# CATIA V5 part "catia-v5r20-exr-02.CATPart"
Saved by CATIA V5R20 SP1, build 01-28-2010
Part number: Part1
Bounding box of the stored display mesh (mm): x 0 to 0, y -1000000 to 1000000, z 0 to 249.999
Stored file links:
  D:\v5_r20\psrt_files_downloaded\c03-catia-v5r20-prt\catia-v5r20-exr-02.CATPart
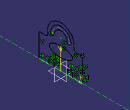
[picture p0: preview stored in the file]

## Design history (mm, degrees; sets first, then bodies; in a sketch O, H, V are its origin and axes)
Body1 (main body)
  Sketch1 on yz-plane, origin (0, 0, 0), H (0, 1, 0), V (0, 0, 1)
    line L1 (0, 0) -> (40, 0)
    point P1 (40, 0)
    line L2 (40, 0) -> (40, 30)
    point P2 (40, 30)
    line L3 (40, 30) -> (70, 30)
    point P3 (70, 30)
    line L4 (70, 30) -> (70, 0)
    point P4 (70, 0)
    line L5 (70, 0) -> (130, 0)
    point P5 (130, 0)
    line L6 (130, 0) -> (130, 140)
    line L7 (130, 140) -> (80.0487, 140)
    line L8 (80.0487, 140) -> (80.0487, 170)
    arc A1 centre (0.0487, 170) radius 80 from (80.0487, 170) to (-79.9513, 170) ccw
    line L9 (-79.9513, 170) -> (-79.9513, 140)
    point P11 (-79.9513, 140)
    line L10 (-79.9513, 140) -> (-130, 140)
    line L11 (-130, 140) -> (-130, 0)
    point P13 (-130, 0)
    point P14 (0, 0)
    construction line L12 through (0, 0) direction (-1, 0)
    point P17 (-40, 0)
    line L13 (0, 0) -> (-40, 0)
    point P18 (-40, 30)
    point P19 (-70, 30)
    point P20 (-70, 0)
    point P21 (-130, 0)
    line L14 (-40, 0) -> (-40, 30)
    line L15 (-40, 30) -> (-70, 30)
    line L16 (-70, 30) -> (-70, 0)
    line L17 (-70, 0) -> (-130, 0)
    construction arc A2 centre (0.0487, 170) radius 49.9513 from (50, 170) to (-49.9026, 170) ccw
    arc A3 centre (50, 170) radius 10.8276 from (60.8276, 170) to (39.1724, 170) cw
    arc A4 centre (-49.9026, 170) radius 10.7303 from (-39.1724, 170) to (-60.6329, 170) cw
    arc A5 centre (0, 170) radius 39.1724 from (39.1724, 170) to (-39.1724, 170) ccw
    arc A6 centre (0.0974, 170) radius 60.7303 from (-60.6329, 170) to (60.8276, 170) cw
    point P28 (0, 100)
    ellipse A7 centre (0, 100) semi-axes 70, 30 rotation 0
    point P29 (70, 100)
    point P30 (0, 130)
    horizontal: L1 H, L3 H, L5 H, L7 H, L10 H
    vertical: L2 V, L4 V, L6 V, L8 V, L11 V
    coincidence: P4 H, P11 L7, P13 H, P28 V, P29 L4, P30 V, A7 P29, A7 P30, O P14, P13 P21
    tangency: A1 L8, L9 A1
    symmetry: O P14 V, H L12 V, P1 P17 V, L1 L13 V, P2 P18 V, P3 P19 V, P4 P20 V, P5 P21 V, L2 L14 V, L3 L15 V, L4 L16 V, L5 L17 V
    parallelism: A7 L7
